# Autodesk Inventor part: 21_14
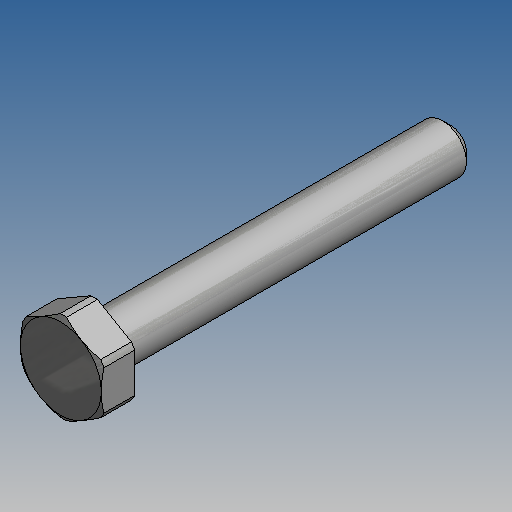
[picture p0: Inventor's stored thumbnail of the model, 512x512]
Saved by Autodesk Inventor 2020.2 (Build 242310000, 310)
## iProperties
Part Number: 21_14
Material: Generic
Document SubType Name: Modeling
Designer: amoles
Appearance: Default
Author: amoles
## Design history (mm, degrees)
feature "Base1"
body "Solid1"
